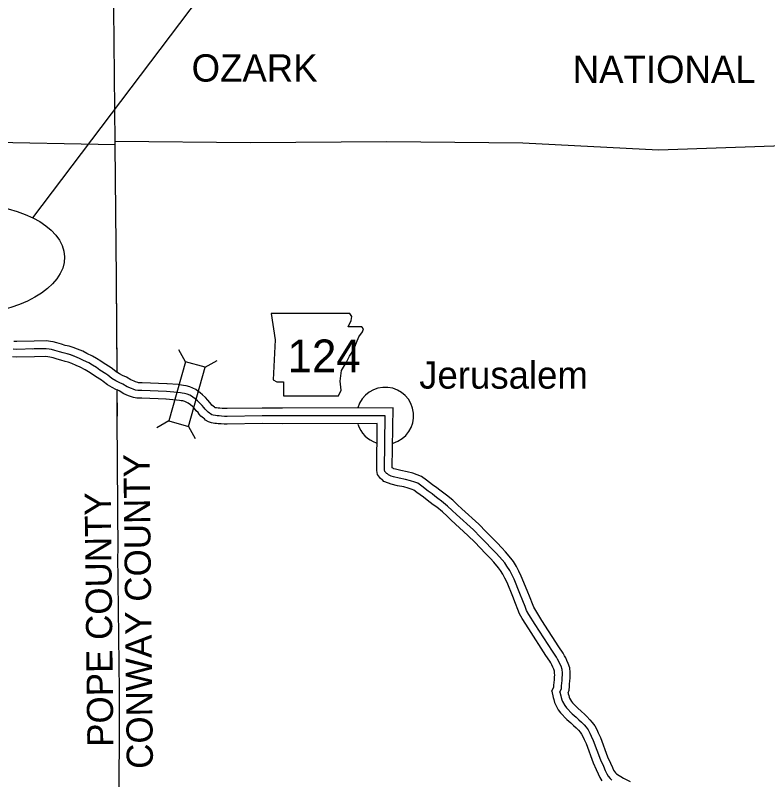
# Model space of a CAD drawing. Extents: x 1373862 to 1376999, y 1168398 to 1170455.
# Drawn here: x 1374264.4 to 1374555, y 1169864.5 to 1170159.8 of the extents above; entities that cross this region are included whole.
import ezdxf

# ---------------------------------------------------------------- set-up
doc = ezdxf.new("R2010")
doc.units = 0
for name, color, linetype in [('Level 10', 7, 'Continuous'), ('Level 2', 7, 'Continuous'), ('Level 20', 7, 'Continuous'), ('Level 21', 7, 'Continuous'), ('Level 24', 7, 'Continuous'), ('Level 59', 7, 'Continuous'), ('Level 8', 7, 'Continuous'), ('R_Draft', 7, 'Continuous')]:
    doc.layers.add(name, color=color, linetype=linetype)

msp = doc.modelspace()

# ---------------------------------------------------------------- linework, layer by layer
at = {"layer": 'Level 10'}
for points in [[(1374303.73, 1170021.81), (1374303.43, 1170022), (1374301.92, 1170023.13), (1374301.01, 1170023.79), (1374298.72, 1170025.22), (1374297.41, 1170026.17), (1374295.82, 1170027.14), (1374294.27, 1170028.1), (1374292.09, 1170029.17), (1374290.44, 1170029.98), (1374288.49, 1170030.8), (1374286.74, 1170031.45), (1374285.19, 1170031.89), (1374283.68, 1170032.27), (1374282.31, 1170032.69), (1374280.52, 1170033.2), (1374279.04, 1170033.56), (1374277.96, 1170033.78), (1374276.47, 1170033.96), (1374271.65, 1170033.86), (1374264.99, 1170033.69), (1374263.86, 1170033.79)], [(1374303.84, 1170014.97), (1374303.3, 1170015.22), (1374301.78, 1170015.96), (1374300.03, 1170017.04), (1374298.37, 1170018.29), (1374297.66, 1170018.81), (1374295.37, 1170020.24), (1374294.09, 1170021.17), (1374292.68, 1170022.02), (1374291.35, 1170022.85), (1374289.45, 1170023.78), (1374287.95, 1170024.51), (1374286.27, 1170025.22), (1374284.87, 1170025.75), (1374283.64, 1170026.09), (1374282.06, 1170026.49), (1374280.61, 1170026.94), (1374278.99, 1170027.4), (1374277.73, 1170027.71), (1374277.01, 1170027.85), (1374276.17, 1170027.95), (1374271.79, 1170027.86), (1374264.81, 1170027.69), (1374263.3, 1170027.82)], [(1374322.95, 1170017.42), (1374313.4, 1170017.82), (1374312.42, 1170017.82), (1374312.06, 1170017.83), (1374311.69, 1170017.91), (1374310.9, 1170018.18), (1374310.32, 1170018.39), (1374309.02, 1170018.91), (1374307.38, 1170019.94), (1374305.86, 1170020.64), (1374304.67, 1170021.22), (1374303.65, 1170021.85)], [(1374322.7, 1170011.43), (1374313.27, 1170011.82), (1374312.29, 1170011.82), (1374311.33, 1170011.86), (1374310.1, 1170012.11), (1374308.92, 1170012.52), (1374308.2, 1170012.77), (1374306.28, 1170013.54), (1374304.52, 1170014.65), (1374303.72, 1170015.02)], [(1374359.73, 1170008.01), (1374346.19, 1170007.84), (1374345.26, 1170007.82), (1374344.33, 1170007.88), (1374343.45, 1170007.96), (1374342.76, 1170008.05), (1374342.1, 1170008.1), (1374341.59, 1170008.17), (1374341.34, 1170008.4), (1374340.83, 1170008.8), (1374340.37, 1170009.19), (1374340.11, 1170009.49), (1374339.55, 1170010.21), (1374338.77, 1170011.03), (1374337.88, 1170012.07), (1374336.75, 1170013.1), (1374335.78, 1170013.91), (1374334.88, 1170014.61), (1374334.1, 1170015.24), (1374332.96, 1170015.76), (1374331.78, 1170016.23), (1374330.4, 1170016.62), (1374329.35, 1170016.81), (1374328.56, 1170016.91), (1374327.33, 1170017.08), (1374323.06, 1170017.41)], [(1374359.81, 1170002.01), (1374346.27, 1170001.84), (1374345.12, 1170001.82), (1374343.89, 1170001.89), (1374342.8, 1170001.99), (1374342.13, 1170002.08), (1374341.46, 1170002.13), (1374340.2, 1170002.3), (1374339.01, 1170002.68), (1374337.9, 1170003.41), (1374337.44, 1170003.84), (1374337.05, 1170004.15), (1374336.13, 1170004.91), (1374335.46, 1170005.71), (1374335, 1170006.29), (1374334.32, 1170007.01), (1374333.57, 1170007.88), (1374332.8, 1170008.58), (1374332.02, 1170009.23), (1374331.15, 1170009.91), (1374330.91, 1170010.1), (1374330.6, 1170010.24), (1374329.85, 1170010.54), (1374329.06, 1170010.77), (1374328.46, 1170010.87), (1374327.78, 1170010.96), (1374326.68, 1170011.11), (1374322.59, 1170011.43)], [(1374477.88, 1169897.98), (1374478.31, 1169898.99), (1374478.38, 1169900.44), (1374478.49, 1169901.5), (1374478.59, 1169902.55), (1374478.65, 1169903.78), (1374478.73, 1169904.79), (1374478.67, 1169905.92), (1374478.56, 1169907.63), (1374477.96, 1169909.37), (1374477.46, 1169910.46), (1374476.97, 1169911.52), (1374476.5, 1169912.36), (1374476.04, 1169913.34), (1374474.31, 1169915.76), (1374467.75, 1169925.96), (1374465.37, 1169929.82), (1374464.61, 1169931.14), (1374464.12, 1169932.44), (1374463.2, 1169934.72), (1374462.09, 1169937.51), (1374459.81, 1169943.1), (1374458.87, 1169945.05), (1374457.93, 1169946.81), (1374456.75, 1169948.7), (1374455.77, 1169950.04), (1374453.69, 1169952.52), (1374452.31, 1169954.01), (1374450.44, 1169955.92), (1374448.13, 1169958.33), (1374446.24, 1169960.28), (1374443.37, 1169963.17), (1374436.83, 1169969.16), (1374435.23, 1169970.62), (1374433.33, 1169972.42), (1374430.9, 1169974.44), (1374429.37, 1169975.54), (1374428.3, 1169976.32), (1374427.2, 1169977.23), (1374425.58, 1169978.4), (1374423.18, 1169980.18), (1374421.34, 1169981.63), (1374419.63, 1169982.26), (1374417.9, 1169982.82), (1374415.76, 1169983.41), (1374413.29, 1169983.85), (1374411.28, 1169984.39), (1374410.63, 1169984.6), (1374410.45, 1169984.67), (1374410.01, 1169984.96), (1374410.29, 1170008.07), (1374367.66, 1170007.99), (1374359.78, 1170008.01)], [(1374471.65, 1169898.65), (1374472.37, 1169900.34), (1374472.39, 1169900.9), (1374472.52, 1169902.09), (1374472.6, 1169902.96), (1374472.66, 1169904.17), (1374472.72, 1169904.85), (1374472.68, 1169905.56), (1374472.62, 1169906.45), (1374472.38, 1169907.15), (1374472.01, 1169907.96), (1374471.63, 1169908.77), (1374471.17, 1169909.6), (1374470.84, 1169910.3), (1374469.34, 1169912.39), (1374462.67, 1169922.76), (1374460.21, 1169926.75), (1374459.17, 1169928.57), (1374458.53, 1169930.26), (1374457.63, 1169932.49), (1374456.53, 1169935.27), (1374454.32, 1169940.67), (1374453.52, 1169942.34), (1374452.74, 1169943.8), (1374451.78, 1169945.33), (1374451.05, 1169946.33), (1374449.19, 1169948.55), (1374447.96, 1169949.87), (1374446.13, 1169951.75), (1374443.81, 1169954.17), (1374441.96, 1169956.08), (1374439.22, 1169958.84), (1374432.78, 1169964.73), (1374431.14, 1169966.22), (1374429.34, 1169967.93), (1374427.23, 1169969.69), (1374425.85, 1169970.68), (1374424.61, 1169971.58), (1374423.53, 1169972.48), (1374422.03, 1169973.56), (1374419.53, 1169975.42), (1374418.38, 1169976.33), (1374417.68, 1169976.59), (1374416.19, 1169977.07), (1374414.43, 1169977.55), (1374411.97, 1169977.99), (1374409.6, 1169978.63), (1374408.56, 1169978.96), (1374406.8, 1169979.7), (1374406.22, 1169980.26), (1374406.05, 1169980.37), (1374405.49, 1169980.82), (1374405.02, 1169981.37), (1374404.32, 1169982.33), (1374403.99, 1169983.92), (1374404.21, 1170002.05), (1374367.65, 1170001.99), (1374359.76, 1170002.01)], [(1374471.63, 1169898.64), (1374472.11, 1169896.23), (1374472.33, 1169895.41), (1374472.61, 1169894.33), (1374473.11, 1169893.25), (1374474.1, 1169891.46), (1374474.96, 1169890.27), (1374477.43, 1169887.74), (1374479.01, 1169886.43), (1374479.98, 1169885.44), (1374480.97, 1169884.54), (1374481.92, 1169883.55), (1374482.55, 1169882.84), (1374483.09, 1169882.09), (1374483.59, 1169881.15), (1374484.09, 1169880.05), (1374484.81, 1169878.44), (1374487.61, 1169871.01), (1374488.78, 1169868.41), (1374489.5, 1169866.75), (1374490.16, 1169865.29), (1374490.89, 1169864.08)], [(1374477.88, 1169897.95), (1374477.95, 1169897.6), (1374478.13, 1169896.95), (1374478.28, 1169896.36), (1374478.46, 1169895.97), (1374479.18, 1169894.68), (1374479.57, 1169894.13), (1374481.49, 1169892.16), (1374483.08, 1169890.86), (1374484.17, 1169889.74), (1374485.14, 1169888.84), (1374486.32, 1169887.63), (1374487.25, 1169886.58), (1374488.21, 1169885.25), (1374488.97, 1169883.81), (1374489.56, 1169882.53), (1374490.36, 1169880.73), (1374493.16, 1169873.31), (1374494.27, 1169870.83), (1374494.99, 1169869.17), (1374495.48, 1169868.08), (1374495.75, 1169867.64), (1374496.25, 1169867.07), (1374496.64, 1169866.71), (1374499.29, 1169865.08), (1374501.82, 1169863.81)]]:
    msp.add_lwpolyline(points, dxfattribs=at)
at = {"layer": 'Level 2'}
for points in [[(1374303.74, 1170021.96), (1374303.55, 1170057.01), (1374303.51, 1170058.05), (1374303.02, 1170109.69), (1374303, 1170110.73), (1374302.44, 1170162.33), (1374302.48, 1170163.35), (1374302.05, 1170186.09)], [(1374303.73, 1170022.77), (1374303.54, 1170057), (1374303.5, 1170058.04), (1374303.02, 1170109.69), (1374303, 1170110.73), (1374302.44, 1170162.33), (1374302.48, 1170163.35), (1374302.05, 1170186.08)], [(1374304.58, 1169845.96), (1374304.62, 1169898.71), (1374304.02, 1169951.43), (1374304.14, 1169952.25), (1374303.73, 1170004.4), (1374303.83, 1170005.3), (1374303.78, 1170014.89)], [(1374304.57, 1169845.95), (1374304.61, 1169898.7), (1374304.01, 1169951.43), (1374304.13, 1169952.25), (1374303.72, 1170004.39), (1374303.82, 1170005.3), (1374303.78, 1170014.28)]]:
    msp.add_lwpolyline(points, dxfattribs=at)
at = {"layer": 'Level 20'}
for p, q in [((1374330.13, 1170025.92), (1374327.54, 1170030.53)), ((1374337.75, 1170023.78), (1374342.35, 1170026.36)), ((1374323.7, 1170003.05), (1374319.1, 1170000.46)), ((1374331.33, 1170000.9), (1374333.91, 1169996.3))]:
    msp.add_line(p, q, dxfattribs=at)
msp.add_lwpolyline([(1374330.13, 1170025.92), (1374323.7, 1170003.05), (1374331.33, 1170000.9), (1374337.75, 1170023.78)], close=True, dxfattribs=at)
at = {"layer": 'Level 21'}
msp.add_lwpolyline([(1374363.19, 1170044.54), (1374364.72, 1170034.39), (1374364.04, 1170018.99), (1374365.39, 1170018.15), (1374367.93, 1170018.15), (1374367.93, 1170012.73), (1374389.25, 1170012.73), (1374390.26, 1170014.93), (1374389.92, 1170018.48), (1374390.43, 1170022.54), (1374392.29, 1170025.76), (1374393.48, 1170028.13), (1374395.17, 1170030.66), (1374396.18, 1170033.37), (1374397.03, 1170035.57), (1374398.55, 1170037.43), (1374398.89, 1170038.62), (1374398.21, 1170039.46), (1374392.97, 1170039.46), (1374394.15, 1170041.83), (1374394.32, 1170043.35), (1374393.62, 1170044.52)], close=True, dxfattribs=at)
at = {"layer": 'Level 24'}
for start, end in [(286.5356, 163.6565), (197.1969, 251.942)]:
    msp.add_arc((1374407.25, 1170005.06), 11, start, end, dxfattribs=at)
at = {"layer": 'Level 59'}
for points in [[(1374304.55, 1170017.95), (1374303.23, 1170018.59), (1374301.73, 1170019.52), (1374300.14, 1170020.71), (1374299.33, 1170021.3), (1374297.04, 1170022.73), (1374295.75, 1170023.67), (1374294.25, 1170024.58), (1374292.81, 1170025.47), (1374290.77, 1170026.47), (1374289.19, 1170027.24), (1374287.38, 1170028.01), (1374285.81, 1170028.6), (1374284.42, 1170028.99), (1374282.87, 1170029.38), (1374281.46, 1170029.81), (1374279.75, 1170030.3), (1374278.39, 1170030.64), (1374277.48, 1170030.82), (1374276.32, 1170030.95), (1374271.72, 1170030.86), (1374264.9, 1170030.69), (1374263.58, 1170030.8)], [(1374322.83, 1170014.42), (1374313.34, 1170014.82), (1374312.36, 1170014.82), (1374311.7, 1170014.85), (1374310.89, 1170015.01), (1374309.91, 1170015.35), (1374309.26, 1170015.58), (1374307.65, 1170016.23), (1374305.95, 1170017.3), (1374304.57, 1170017.93), (1374303.22, 1170018.58), (1374301.72, 1170019.52), (1374300.14, 1170020.71), (1374299.33, 1170021.29), (1374297.04, 1170022.73), (1374295.74, 1170023.66), (1374294.24, 1170024.57), (1374292.8, 1170025.47), (1374290.76, 1170026.47), (1374289.19, 1170027.24), (1374287.37, 1170028), (1374285.8, 1170028.59), (1374284.41, 1170028.99), (1374282.87, 1170029.38), (1374281.46, 1170029.81), (1374279.75, 1170030.3), (1374278.38, 1170030.63), (1374277.48, 1170030.81), (1374276.31, 1170030.95), (1374271.71, 1170030.86), (1374271.2, 1170030.85)], [(1374322.83, 1170014.42), (1374313.34, 1170014.82), (1374312.36, 1170014.82), (1374311.7, 1170014.85), (1374310.89, 1170015.01), (1374309.91, 1170015.35), (1374309.26, 1170015.58), (1374307.65, 1170016.23), (1374305.95, 1170017.3), (1374304.57, 1170017.93), (1374303.71, 1170018.35)], [(1374359.77, 1170005.01), (1374346.23, 1170004.84), (1374345.19, 1170004.82), (1374344.11, 1170004.89), (1374343.13, 1170004.97), (1374342.44, 1170005.06), (1374341.78, 1170005.11), (1374340.86, 1170005.24), (1374340.32, 1170005.41), (1374339.75, 1170005.79), (1374339.39, 1170006.12), (1374338.94, 1170006.47), (1374338.25, 1170007.05), (1374337.78, 1170007.6), (1374337.27, 1170008.25), (1374336.54, 1170009.02), (1374335.73, 1170009.97), (1374334.78, 1170010.84), (1374333.9, 1170011.57), (1374333.01, 1170012.26), (1374332.51, 1170012.67), (1374331.78, 1170013), (1374330.82, 1170013.39), (1374329.73, 1170013.69), (1374328.91, 1170013.84), (1374328.17, 1170013.93), (1374327, 1170014.09), (1374322.83, 1170014.42)], [(1374474.76, 1169898.29), (1374475.34, 1169899.67), (1374475.39, 1169900.67), (1374475.51, 1169901.79), (1374475.59, 1169902.76), (1374475.66, 1169903.98), (1374475.72, 1169904.82), (1374475.67, 1169905.74), (1374475.59, 1169907.04), (1374475.17, 1169908.26), (1374474.74, 1169909.21), (1374474.3, 1169910.15), (1374473.83, 1169910.98), (1374473.44, 1169911.82), (1374471.83, 1169914.08), (1374465.21, 1169924.36), (1374462.79, 1169928.29), (1374461.89, 1169929.86), (1374461.32, 1169931.35), (1374460.41, 1169933.6), (1374459.31, 1169936.39), (1374457.07, 1169941.89), (1374456.2, 1169943.7), (1374455.33, 1169945.31), (1374454.27, 1169947.01), (1374453.41, 1169948.18), (1374451.44, 1169950.54), (1374450.13, 1169951.94), (1374448.29, 1169953.84), (1374445.97, 1169956.25), (1374444.1, 1169958.18), (1374441.3, 1169961.01), (1374434.81, 1169966.94), (1374433.18, 1169968.42), (1374431.34, 1169970.18), (1374429.07, 1169972.07), (1374427.61, 1169973.11), (1374426.46, 1169973.95), (1374425.36, 1169974.86), (1374423.81, 1169975.98), (1374421.36, 1169977.8), (1374419.86, 1169978.98), (1374418.65, 1169979.43), (1374417.05, 1169979.94), (1374415.1, 1169980.48), (1374412.63, 1169980.92), (1374410.44, 1169981.51), (1374409.6, 1169981.78), (1374408.49, 1169982.24), (1374408.1, 1169982.62), (1374407.8, 1169982.81), (1374407.58, 1169982.99), (1374407.37, 1169983.23), (1374407.13, 1169983.57), (1374407, 1169984.21), (1374407.25, 1170005.06), (1374367.65, 1170004.99), (1374359.77, 1170005.01)], [(1374474.76, 1169898.29), (1374475.03, 1169896.92), (1374475.23, 1169896.18), (1374475.45, 1169895.34), (1374475.78, 1169894.61), (1374476.64, 1169893.07), (1374477.26, 1169892.2), (1374479.46, 1169889.95), (1374481.05, 1169888.65), (1374482.07, 1169887.59), (1374483.06, 1169886.69), (1374484.12, 1169885.59), (1374484.9, 1169884.71), (1374485.65, 1169883.67), (1374486.28, 1169882.48), (1374486.83, 1169881.29), (1374487.59, 1169879.59), (1374490.39, 1169872.16), (1374491.53, 1169869.62), (1374492.25, 1169867.96), (1374492.82, 1169866.69), (1374493.32, 1169865.86), (1374494.1, 1169864.98), (1374494.82, 1169864.31)]]:
    msp.add_lwpolyline(points, dxfattribs=at)
at = {"layer": 'Level 8'}
for points in [[(1374303.02, 1170109.69), (1374250.22, 1170110.79)], [(1374604.21, 1170109.08), (1374564.79, 1170109.52), (1374512.83, 1170107.65), (1374460.36, 1170110.41), (1374407.96, 1170110.86), (1374355.11, 1170110.55), (1374302.93, 1170110.96)]]:
    msp.add_lwpolyline(points, dxfattribs=at)
at = {"layer": 'R_Draft'}
msp.add_line((1374271.24, 1170081.51), (1374519.92, 1170410.99), dxfattribs=at)
msp.add_ellipse((1374242.83, 1170065.49), major_axis=(40.62, 1), ratio=0.533954, dxfattribs=at)

# ---------------------------------------------------------------- texts
at = {"layer": 'Level 21'}
msp.add_text('124', height=12.672, dxfattribs=at).set_placement((1374369.56, 1170021.85))
at = {"layer": 'Level 24'}
msp.add_text('Jerusalem', height=10.56, dxfattribs=at).set_placement((1374420.4, 1170015.54))
at = {"layer": 'Level 8'}
for s, p in [('OZARK', (1374332.51, 1170134.16)), ('NATIONAL', (1374479.69, 1170133.65))]:
    msp.add_text(s, height=10.56, dxfattribs=at).set_placement(p)
at = {"layer": 'R_Draft'}
for s, p in [('CONWAY COUNTY', (1374317.59, 1169868.7)), ('POPE COUNTY', (1374302.33, 1169877.2))]:
    msp.add_text(s, height=10.1073, rotation=90.6173, dxfattribs=at).set_placement(p)

doc.saveas('drawing.dxf')
